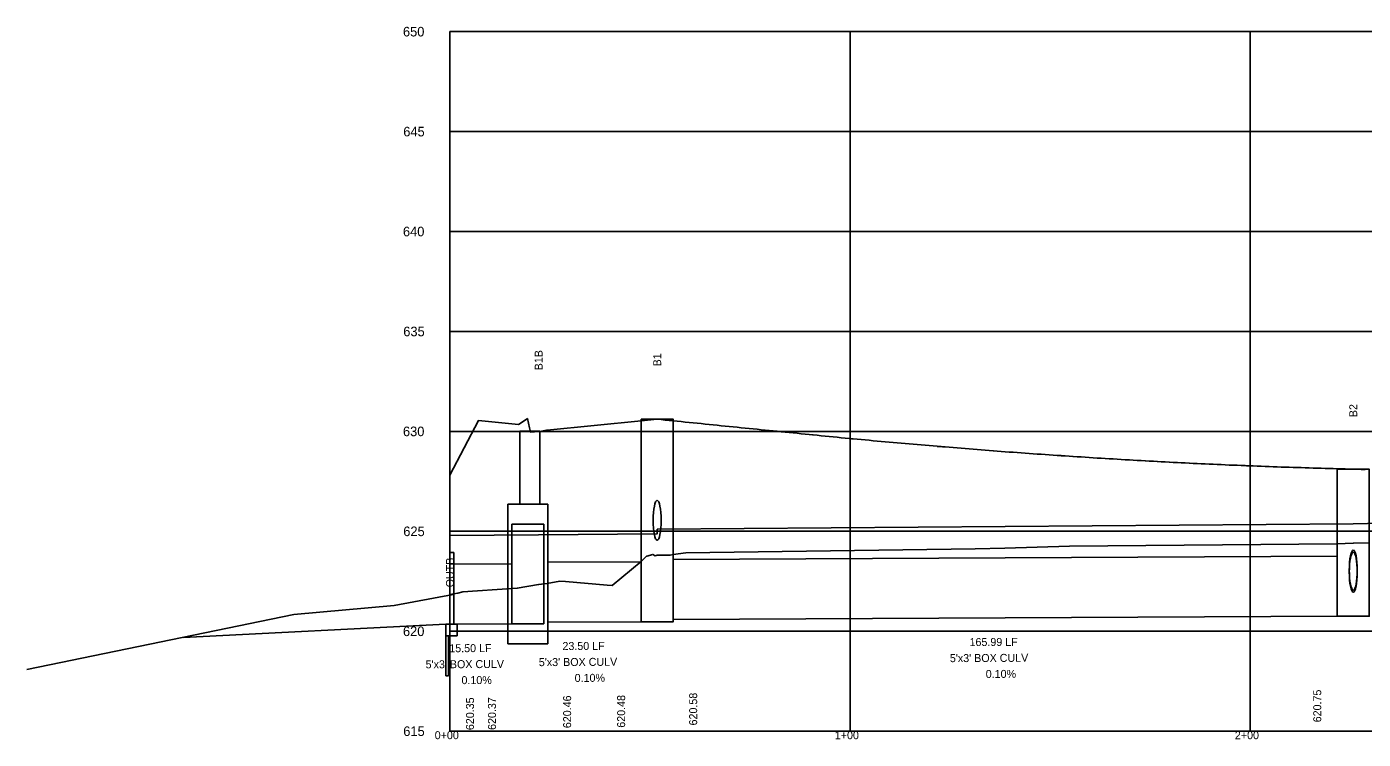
# Model space of a CAD drawing. Extents: x 2254979 to 2278074, y 13790855 to 13792793.
# Drawn here: x 2259854.9 to 2260189, y 13792139.4 to 13792317.7 of the extents above; entities that cross this region are included whole.
import ezdxf

# ---------------------------------------------------------------- set-up
doc = ezdxf.new("R2010")
doc.units = 0
for name, color, linetype in [('blank4', 7, 'Continuous'), ('D_DRN_PIPE', 7, 'Continuous'), ('D_DRN_PROF_HGL', 7, 'Continuous'), ('D_PROF_1', 7, 'Continuous'), ('D_PROF_NOTES_1', 7, 'Continuous'), ('Default', 7, 'Continuous'), ('Drain_PipeInside', 7, 'Continuous'), ('E_Terrain', 7, 'Continuous'), ('E_Terrain_Contours', 7, 'Continuous'), ('Inlet', 7, 'Continuous'), ('z - Construction', 7, 'Continuous')]:
    doc.layers.add(name, color=color, linetype=linetype)

msp = doc.modelspace()

# ---------------------------------------------------------------- linework, layer by layer
at = {"layer": 'blank4'}
msp.add_lwpolyline([(2259960.69, 13792141.44), (2259960.69, 13792316.44), (2261351.48, 13792316.44), (2261351.48, 13792141.44)], close=True, dxfattribs=at)
at = {"layer": 'D_DRN_PIPE'}
msp.add_line((2259960.69, 13792141.46), (2259960.69, 13792141.44), dxfattribs=at)
at = {"layer": 'D_DRN_PROF_HGL'}
for p, q in [((2260186.47, 13792193.36), (2260186.47, 13792193.28)), ((2259982.86, 13792190.63), (2259982.86, 13792190.56)), ((2260012.48, 13792192.02), (2260012.48, 13792191.96))]:
    msp.add_line(p, q, dxfattribs=at)
for points in [[(2260186.47, 13792193.28), (2260364.67, 13792197.49), (2260364.67, 13792198.22)], [(2260012.48, 13792191.96), (2260186.47, 13792193.32), (2260186.47, 13792193.36)], [(2259960.69, 13792190.39), (2259982.86, 13792190.6), (2259982.86, 13792190.63)], [(2259982.86, 13792190.56), (2260012.48, 13792190.82), (2260012.48, 13792192.02)]]:
    msp.add_lwpolyline(points, dxfattribs=at)
at = {"layer": 'D_PROF_1'}
for p, q in [((2259960.69, 13792205.45), (2259960.69, 13792186.09)), ((2259960.69, 13792186.11), (2259960.68, 13792168.2)), ((2259961.69, 13792186.11), (2259960.69, 13792186.11)), ((2259961.68, 13792168.19), (2259961.69, 13792186.12)), ((2259959.68, 13792168.2), (2259894.05, 13792164.92)), ((2259959.68, 13792155.28), (2259959.68, 13792168.2)), ((2259962.52, 13792168.2), (2259959.68, 13792168.2)), ((2259962.52, 13792165.28), (2259962.52, 13792168.2)), ((2259962.52, 13792165.28), (2259959.68, 13792165.28)), ((2259960.35, 13792155.28), (2259960.35, 13792165.27)), ((2259960.35, 13792155.28), (2259959.68, 13792155.28))]:
    msp.add_line(p, q, dxfattribs=at)
msp.add_lwpolyline([(2259960.69, 13792205.45), (2259967.84, 13792219.17), (2259976.19, 13792218.33), (2259976.19, 13792218.33), (2259977.86, 13792218.15), (2259979.47, 13792219.24), (2259980.03, 13792219.63), (2259980.56, 13792217.34), (2259980.57, 13792217.3), (2259980.57, 13792217.29), (2259980.63, 13792217.02), (2259980.8, 13792216.31), (2259980.8, 13792216.28), (2259982.86, 13792216.43), (2259982.86, 13792216.43), (2259983.56, 13792216.53), (2259984.82, 13792216.71), (2259984.98, 13792216.73), (2259984.98, 13792216.73), (2259984.98, 13792216.73), (2260008.48, 13792219.08), (2260008.48, 13792219.08), (2260012.48, 13792219.48), (2260012.48, 13792219.48), (2260013.48, 13792219.38), (2260014.48, 13792219.28), (2260015.48, 13792219.18), (2260016.48, 13792219.08), (2260016.48, 13792219.08), (2260017.48, 13792218.98), (2260018.48, 13792218.88), (2260018.48, 13792218.88), (2260019.48, 13792218.78), (2260019.48, 13792218.78), (2260019.48, 13792218.78), (2260020.48, 13792218.68), (2260020.48, 13792218.68), (2260021.48, 13792218.58), (2260021.48, 13792218.58), (2260022.48, 13792218.48), (2260023.48, 13792218.38), (2260023.48, 13792218.38), (2260023.48, 13792218.38), (2260024.48, 13792218.28), (2260025.48, 13792218.18), (2260025.48, 13792218.18), (2260025.48, 13792218.18), (2260026.48, 13792218.08), (2260027.48, 13792217.97), (2260027.48, 13792217.97), (2260027.48, 13792217.97), (2260028.48, 13792217.87), (2260029.48, 13792217.77), (2260029.48, 13792217.77), (2260029.48, 13792217.77), (2260030.48, 13792217.67), (2260030.48, 13792217.67), (2260031.48, 13792217.57), (2260032.48, 13792217.47), (2260032.48, 13792217.47), (2260032.48, 13792217.47), (2260033.48, 13792217.37), (2260033.48, 13792217.37), (2260034.48, 13792217.27), (2260035.48, 13792217.17), (2260035.48, 13792217.17), (2260035.48, 13792217.17), (2260036.48, 13792217.07), (2260037.47, 13792216.97), (2260037.48, 13792216.97), (2260038.47, 13792216.87), (2260038.48, 13792216.87), (2260038.48, 13792216.87), (2260039.48, 13792216.77), (2260040.47, 13792216.67), (2260040.48, 13792216.67), (2260041.47, 13792216.57), (2260041.48, 13792216.57), (2260042.47, 13792216.47), (2260042.48, 13792216.47), (2260042.48, 13792216.47), (2260043.48, 13792216.37), (2260043.48, 13792216.37), (2260044.48, 13792216.26), (2260045.47, 13792216.16), (2260045.48, 13792216.16), (2260046.47, 13792216.06), (2260046.48, 13792216.06), (2260047.47, 13792215.96), (2260047.48, 13792215.96), (2260047.48, 13792215.96), (2260048.48, 13792215.86), (2260048.48, 13792215.86), (2260049.48, 13792215.76), (2260049.48, 13792215.76), (2260050.48, 13792215.66), (2260051.33, 13792215.58), (2260051.34, 13792215.58), (2260051.48, 13792215.56), (2260051.48, 13792215.56), (2260052.47, 13792215.46), (2260052.48, 13792215.46), (2260052.48, 13792215.46), (2260053.48, 13792215.36), (2260053.48, 13792215.36), (2260054.48, 13792215.26), (2260054.48, 13792215.26), (2260055.48, 13792215.16), (2260056.47, 13792215.07), (2260056.48, 13792215.07), (2260056.48, 13792215.06), (2260057.48, 13792214.97), (2260057.48, 13792214.97), (2260058.48, 13792214.87), (2260059.47, 13792214.77), (2260059.48, 13792214.77), (2260059.48, 13792214.77), (2260060.48, 13792214.68), (2260060.48, 13792214.68), (2260061.09, 13792214.62), (2260061.48, 13792214.58), (2260061.48, 13792214.58), (2260062.47, 13792214.49), (2260062.48, 13792214.49), (2260062.48, 13792214.49), (2260063.48, 13792214.39), (2260064.47, 13792214.3), (2260064.48, 13792214.3), (2260065.47, 13792214.21), (2260065.48, 13792214.21), (2260066.47, 13792214.11), (2260066.48, 13792214.11), (2260066.49, 13792214.11), (2260067.48, 13792214.02), (2260067.49, 13792214.02), (2260068.48, 13792213.93), (2260069.47, 13792213.84), (2260069.48, 13792213.84), (2260070.47, 13792213.75), (2260070.48, 13792213.75), (2260070.49, 13792213.75), (2260071.48, 13792213.66), (2260072.47, 13792213.57), (2260072.48, 13792213.57), (2260072.49, 13792213.57), (2260073.48, 13792213.48), (2260073.49, 13792213.48), (2260074.48, 13792213.39), (2260075.47, 13792213.31), (2260075.48, 13792213.3), (2260075.49, 13792213.3), (2260076.48, 13792213.22), (2260076.49, 13792213.22), (2260077.48, 13792213.13), (2260078.47, 13792213.04), (2260078.48, 13792213.04), (2260079.47, 13792212.96), (2260079.48, 13792212.96), (2260079.49, 13792212.96), (2260080.48, 13792212.87), (2260080.49, 13792212.87), (2260081.48, 13792212.79), (2260082.47, 13792212.71), (2260082.48, 13792212.7), (2260082.49, 13792212.7), (2260083.48, 13792212.62), (2260083.48, 13792212.62), (2260083.84, 13792212.59), (2260084.47, 13792212.54), (2260084.48, 13792212.54), (2260084.49, 13792212.54), (2260085.48, 13792212.46), (2260086.47, 13792212.37), (2260086.48, 13792212.37), (2260087.47, 13792212.29), (2260087.48, 13792212.29), (2260088.47, 13792212.21), (2260088.48, 13792212.21), (2260088.49, 13792212.21), (2260089.48, 13792212.13), (2260089.49, 13792212.13), (2260090.48, 13792212.05), (2260091.47, 13792211.97), (2260091.48, 13792211.97), (2260092.47, 13792211.89), (2260092.48, 13792211.89), (2260092.49, 13792211.89), (2260093.48, 13792211.82), (2260094.47, 13792211.74), (2260094.48, 13792211.74), (2260094.49, 13792211.74), (2260095.48, 13792211.66), (2260096.47, 13792211.59), (2260096.48, 13792211.58), (2260097.47, 13792211.51), (2260097.48, 13792211.51), (2260097.49, 13792211.51), (2260098.48, 13792211.43), (2260098.49, 13792211.43), (2260099.48, 13792211.36), (2260100.47, 13792211.28), (2260100.48, 13792211.28), (2260101.47, 13792211.21), (2260101.48, 13792211.21), (2260102.47, 13792211.14), (2260102.48, 13792211.14), (2260102.49, 13792211.14), (2260103.48, 13792211.06), (2260103.49, 13792211.06), (2260104.48, 13792210.99), (2260105.47, 13792210.92), (2260105.48, 13792210.92), (2260105.49, 13792210.92), (2260106.48, 13792210.85), (2260107.47, 13792210.78), (2260107.48, 13792210.78), (2260107.49, 13792210.78), (2260108.48, 13792210.71), (2260108.49, 13792210.71), (2260109.48, 13792210.64), (2260110.47, 13792210.57), (2260110.48, 13792210.57), (2260111.46, 13792210.5), (2260111.48, 13792210.5), (2260112.46, 13792210.43), (2260112.48, 13792210.43), (2260112.49, 13792210.43), (2260113.48, 13792210.37), (2260113.49, 13792210.36), (2260114.48, 13792210.3), (2260115.46, 13792210.23), (2260115.48, 13792210.23), (2260115.49, 13792210.23), (2260116.34, 13792210.18), (2260116.48, 13792210.17), (2260116.48, 13792210.17), (2260116.49, 13792210.17), (2260117.48, 13792210.1), (2260117.49, 13792210.1), (2260118.48, 13792210.04), (2260119.46, 13792209.97), (2260119.48, 13792209.97), (2260119.49, 13792209.97), (2260120.48, 13792209.91), (2260121.46, 13792209.85), (2260121.48, 13792209.85), (2260121.49, 13792209.85), (2260122.48, 13792209.78), (2260122.49, 13792209.78), (2260123.48, 13792209.72), (2260124.46, 13792209.66), (2260124.48, 13792209.66), (2260125.46, 13792209.6), (2260125.48, 13792209.6), (2260126.46, 13792209.54), (2260126.48, 13792209.54), (2260127.46, 13792209.48), (2260127.48, 13792209.48), (2260127.49, 13792209.48), (2260128.48, 13792209.42), (2260129.46, 13792209.36), (2260129.48, 13792209.36), (2260129.49, 13792209.36), (2260130.48, 13792209.3), (2260130.5, 13792209.3), (2260131.48, 13792209.25), (2260132.46, 13792209.19), (2260132.48, 13792209.19), (2260132.5, 13792209.19), (2260133.48, 13792209.13), (2260134.46, 13792209.08), (2260134.48, 13792209.08), (2260134.5, 13792209.07), (2260135.48, 13792209.02), (2260135.5, 13792209.02), (2260136.48, 13792208.96), (2260136.5, 13792208.96), (2260137.48, 13792208.91), (2260137.5, 13792208.91), (2260138.48, 13792208.86), (2260139.46, 13792208.8), (2260139.48, 13792208.8), (2260140.46, 13792208.75), (2260140.48, 13792208.75), (2260140.5, 13792208.75), (2260141.48, 13792208.7), (2260141.9, 13792208.68), (2260141.9, 13792208.68), (2260142.47, 13792208.65), (2260142.48, 13792208.65), (2260142.5, 13792208.65), (2260143.48, 13792208.6), (2260143.5, 13792208.59), (2260144.48, 13792208.54), (2260145.46, 13792208.5), (2260145.48, 13792208.49), (2260145.49, 13792208.49), (2260146.48, 13792208.45), (2260147.46, 13792208.4), (2260147.48, 13792208.4), (2260147.49, 13792208.4), (2260148.48, 13792208.35), (2260148.48, 13792208.35), (2260148.83, 13792208.33), (2260149.46, 13792208.3), (2260149.48, 13792208.3), (2260149.49, 13792208.3), (2260150.47, 13792208.26), (2260151.46, 13792208.21), (2260151.47, 13792208.21), (2260152.46, 13792208.17), (2260152.47, 13792208.16), (2260152.49, 13792208.16), (2260153.47, 13792208.12), (2260154.46, 13792208.08), (2260154.47, 13792208.08), (2260154.49, 13792208.08), (2260155.47, 13792208.03), (2260156.46, 13792207.99), (2260156.47, 13792207.99), (2260156.49, 13792207.99), (2260157.47, 13792207.95), (2260157.49, 13792207.95), (2260158.47, 13792207.91), (2260159.45, 13792207.87), (2260159.47, 13792207.87), (2260159.47, 13792207.87), (2260159.75, 13792207.86), (2260160.46, 13792207.83), (2260160.47, 13792207.83), (2260160.49, 13792207.83), (2260161.47, 13792207.79), (2260161.48, 13792207.79), (2260162.47, 13792207.75), (2260162.48, 13792207.75), (2260163.47, 13792207.71), (2260164.46, 13792207.67), (2260164.47, 13792207.67), (2260165.46, 13792207.64), (2260165.47, 13792207.64), (2260165.48, 13792207.64), (2260166.47, 13792207.6), (2260167.46, 13792207.57), (2260167.47, 13792207.57), (2260168.46, 13792207.53), (2260168.47, 13792207.53), (2260169.46, 13792207.5), (2260169.47, 13792207.5), (2260169.48, 13792207.5), (2260170.47, 13792207.46), (2260171.46, 13792207.43), (2260171.47, 13792207.43), (2260172.46, 13792207.4), (2260172.47, 13792207.4), (2260172.48, 13792207.4), (2260173.47, 13792207.37), (2260173.48, 13792207.37), (2260174.47, 13792207.34), (2260175.46, 13792207.31), (2260175.47, 13792207.31), (2260175.47, 13792207.31), (2260176.47, 13792207.28), (2260176.47, 13792207.28), (2260177.47, 13792207.25), (2260177.59, 13792207.24), (2260177.6, 13792207.24), (2260177.6, 13792207.24), (2260178.47, 13792207.22), (2260178.47, 13792207.22), (2260179.47, 13792207.19), (2260179.47, 13792207.19), (2260180.47, 13792207.16), (2260181.33, 13792207.14), (2260181.33, 13792207.14), (2260181.33, 13792207.14), (2260181.47, 13792207.14), (2260182.47, 13792207.11), (2260182.47, 13792207.11), (2260182.47, 13792207.11), (2260183.47, 13792207.08), (2260184.47, 13792207.05), (2260185.47, 13792207.02), (2260186.47, 13792206.99), (2260186.47, 13792206.99), (2260187.47, 13792206.96), (2260188.47, 13792206.93), (2260189.47, 13792206.9)], dxfattribs=at)
at = {"layer": 'Default'}
for p, q in [((2260060.69, 13792141.44), (2260060.69, 13792316.44)), ((2260160.69, 13792141.44), (2260160.69, 13792316.44))]:
    msp.add_line(p, q, dxfattribs=at)
at = {"layer": 'Drain_PipeInside'}
for p, q in [((2259960.69, 13792183.19), (2259976.19, 13792183.27)), ((2259984.98, 13792183.72), (2260008.48, 13792183.84)), ((2260016.48, 13792184.36), (2260182.47, 13792185.19)), ((2259984.98, 13792168.72), (2260008.48, 13792168.84)), ((2260016.48, 13792169.36), (2260182.47, 13792170.19)), ((2259960.69, 13792168.19), (2259976.19, 13792168.27))]:
    msp.add_line(p, q, dxfattribs=at)
for centre in [(2260012.48, 13792194.2), (2260186.47, 13792181.74), (2260186.47, 13792181.22)]:
    msp.add_ellipse(centre, major_axis=(0, 5), ratio=0.2, dxfattribs=at)
at = {"layer": 'E_Terrain'}
msp.add_lwpolyline([(2259960.69, 13792175.66), (2259961.13, 13792175.7), (2259961.57, 13792175.78), (2259962.63, 13792175.94), (2259963.9, 13792176.29), (2259976.19, 13792177.1), (2259976.19, 13792177.1), (2259977.5, 13792177.19), (2259982.86, 13792178.12), (2259982.86, 13792178.12), (2259984.98, 13792178.37), (2259984.98, 13792178.37), (2259988.19, 13792178.94), (2259989.59, 13792178.9), (2259999.98, 13792177.95), (2260001.27, 13792177.9), (2260008.48, 13792183.9), (2260008.48, 13792183.9), (2260008.63, 13792184.02), (2260009.82, 13792185.26), (2260009.89, 13792185.26), (2260011.43, 13792185.67), (2260012.02, 13792185.33), (2260012.48, 13792185.46), (2260012.48, 13792185.46), (2260015.72, 13792185.51), (2260016.48, 13792185.62), (2260016.48, 13792185.62), (2260019.68, 13792186.05), (2260091.99, 13792187.07), (2260099.4, 13792187.24), (2260115.51, 13792187.7), (2260182.47, 13792188.3), (2260182.47, 13792188.3), (2260186.47, 13792188.44), (2260186.47, 13792188.44), (2260190.47, 13792188.59)], dxfattribs=at)
at = {"layer": 'E_Terrain_Contours'}
msp.add_lwpolyline([(2259961.48, 13792175.66), (2259946.72, 13792172.87), (2259921.68, 13792170.64), (2259854.9, 13792156.91)], dxfattribs=at)
at = {"layer": 'Inlet'}
for p, q in [((2259978.19, 13792198.27), (2259978.19, 13792216.53)), ((2259983.19, 13792216.53), (2259978.19, 13792216.53)), ((2259983.19, 13792198.27), (2259983.19, 13792216.53)), ((2259975.19, 13792198.27), (2259985.19, 13792198.27)), ((2259975.19, 13792198.27), (2259975.19, 13792163.27)), ((2259985.19, 13792163.27), (2259985.19, 13792198.27)), ((2259976.19, 13792193.27), (2259984.19, 13792193.27)), ((2259976.19, 13792193.27), (2259976.19, 13792168.27)), ((2259984.19, 13792168.27), (2259984.19, 13792193.27)), ((2259976.19, 13792168.27), (2259984.19, 13792168.27)), ((2259975.19, 13792163.27), (2259985.19, 13792163.27))]:
    msp.add_line(p, q, dxfattribs=at)
for points in [[(2260008.48, 13792219.48), (2260016.48, 13792219.48), (2260016.48, 13792168.84), (2260008.48, 13792168.84)], [(2260182.47, 13792206.99), (2260190.47, 13792206.99), (2260190.47, 13792170.19), (2260182.47, 13792170.19)], [(2259960.69, 13792166.44), (2259960.69, 13792166.44), (2259960.69, 13792168.19), (2259960.69, 13792168.19)]]:
    msp.add_lwpolyline(points, close=True, dxfattribs=at)
at = {"layer": 'z - Construction'}
for p, q in [((2259960.69, 13792291.44), (2261351.48, 13792291.44)), ((2259960.69, 13792266.44), (2261351.48, 13792266.44)), ((2259960.69, 13792241.44), (2261351.48, 13792241.44)), ((2259960.69, 13792216.44), (2261351.48, 13792216.44)), ((2259960.69, 13792191.44), (2261351.48, 13792191.44)), ((2259960.69, 13792166.44), (2261351.48, 13792166.44))]:
    msp.add_line(p, q, dxfattribs=at)

# ---------------------------------------------------------------- texts
at = {"layer": 'D_PROF_NOTES_1'}
for s, rotation, p in [('B1B', 90, (2259983.86, 13792231.72)), ('B1', 90, (2260013.48, 13792232.71)), ('B2', 90, (2260187.47, 13792220)), ('OUTB', 90, (2259961.69, 13792177.43)), ('15.50 LF', 0.2865, (2259960.52, 13792161.19)), ('23.50 LF', 0.2865, (2259988.81, 13792161.74)), ('165.99 LF', 0.2865, (2260090.56, 13792162.73)), ("5'x3' BOX CULV", 0.2865, (2259954.6, 13792157.16)), ("5'x3' BOX CULV", 0.2865, (2259982.9, 13792157.71)), ("5'x3' BOX CULV", 0.2865, (2260085.64, 13792158.71)), ('0.10%', 0.2865, (2259991.86, 13792153.76)), ('0.10%', 0.2865, (2260094.61, 13792154.75)), ('0.10%', 0.2865, (2259963.57, 13792153.21)), ('620.35', 90, (2259966.69, 13792141.71)), ('620.37', 90, (2259972.19, 13792141.76)), ('620.46', 90, (2259990.98, 13792142.2)), ('620.48', 90, (2260004.48, 13792142.31)), ('620.58', 90, (2260022.48, 13792142.88)), ('620.75', 90, (2260178.47, 13792143.66))]:
    msp.add_text(s, height=2, rotation=rotation, dxfattribs=at).set_placement(p)
at = {"layer": 'Default'}
for s, height, p in [('650', 2.4, (2259948.94, 13792315.24)), ('645', 2.4, (2259949.02, 13792290.24)), ('640', 2.4, (2259948.94, 13792265.24)), ('635', 2.4, (2259949.02, 13792240.24)), ('630', 2.4, (2259948.94, 13792215.24)), ('625', 2.4, (2259949.02, 13792190.24)), ('620', 2.4, (2259948.94, 13792165.24)), ('615', 2.4, (2259949.02, 13792140.24)), ('0+00', 2, (2259956.88, 13792139.44)), ('1+00', 2, (2260056.88, 13792139.44)), ('2+00', 2, (2260156.88, 13792139.44))]:
    msp.add_text(s, height=height, dxfattribs=at).set_placement(p)

doc.saveas('drawing.dxf')
